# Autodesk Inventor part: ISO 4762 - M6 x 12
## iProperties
Created: 2008-08
Part Number: ISO 4762 - M6 x 12
Material: BgAAAEgAAABOAEEATQBFAFMACgBNAGEAdABlAHIAaQBhAGwAcwAKADEAOgBTAHQAZQBlAGwALAAgAE0AaQBsAGQACgAKAEUATgBEAAoAAAA=
Description: Innensechskantschraube
Vendor: Autodesk Inc.
Document SubType Name: Modeling
Standard: ISO 4762
Designer: U.Rapp
Standards Organization: DIN
Language: de-DE
Size Designation: M6 x 12
Categories: <MemberInstance Version="R10.0.0"><Categories><Category DisplayName="Schrauben" InternalName="e4da775c-781d-43d5-af7c-5136215cf5a6" Mnemonic="FSTN"><Category Di
Author: U.Rapp
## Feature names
1. Körper [Revolution]
2. Loch [Extrusion]
3. Rundung1 [Fillet]
4. Fase1 [Chamfer]
